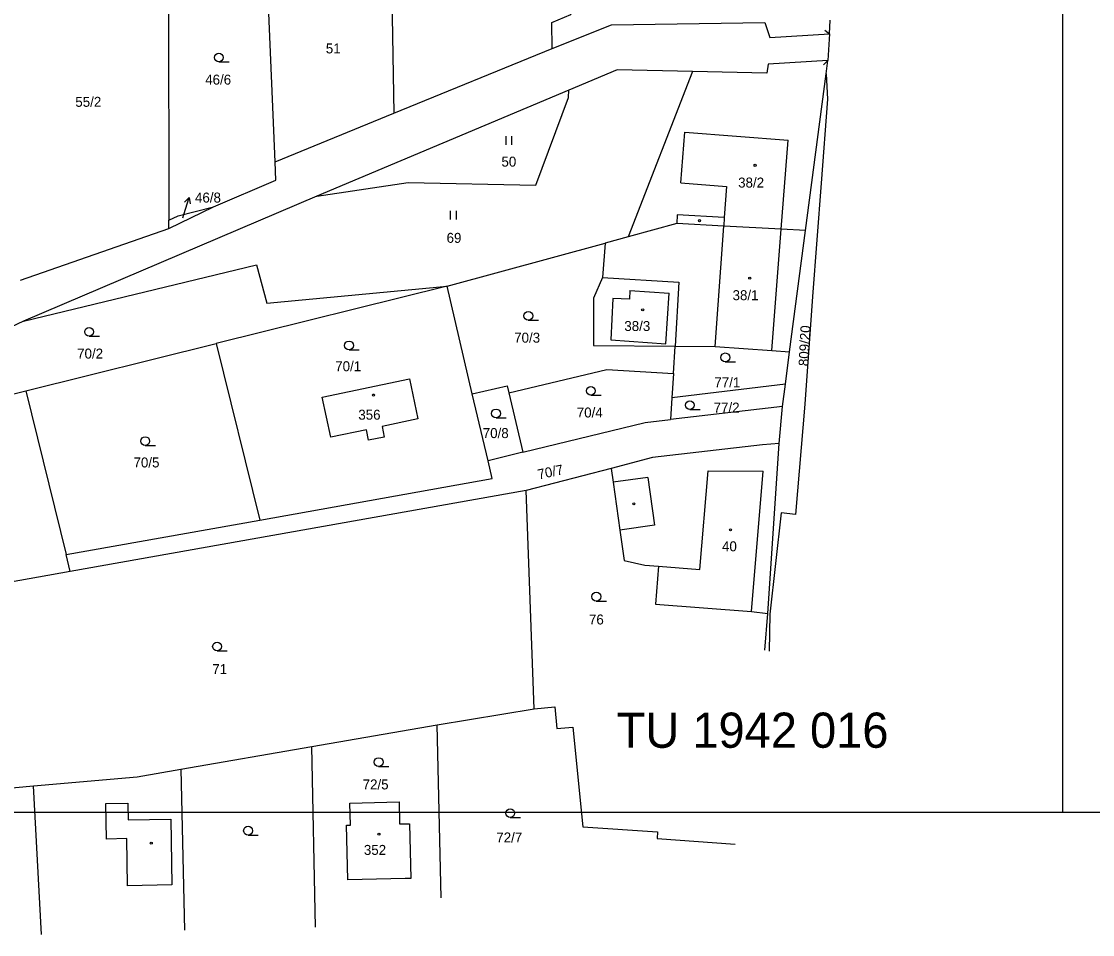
# Model space of a CAD drawing. Extents: x -553916 to -552953, y -1067469 to -1066637.
# Drawn here: x -553477.6 to -553294.9, y -1067431.1 to -1067275.4 of the extents above; entities that cross this region are included whole.
import ezdxf

# ---------------------------------------------------------------- set-up
doc = ezdxf.new("R2010")
doc.units = 0
for name, color, linetype in [('Hranice parcel', 7, 'Continuous'), ('Parcelní čísla', 7, 'Continuous'), ('Pop  PČ popisy', 7, 'Continuous'), ('Vnitřní kresba', 7, 'Continuous'), ('Vrstva 1', 7, 'Continuous'), ('Vrstva 2', 7, 'Continuous'), ('Značky budov', 7, 'Continuous'), ('Značky kultur', 7, 'Continuous')]:
    doc.layers.add(name, color=color, linetype=linetype)

msp = doc.modelspace()

# ---------------------------------------------------------------- linework, layer by layer
at = {"layer": 'Hranice parcel'}
for p, q in [((-553452.56, -1067263.4), (-553452.48, -1067309.26)), ((-553434.32, -1067299.29), (-553435.83, -1067263.59)), ((-553414.54, -1067263.83), (-553414.1, -1067291.02)), ((-553339.78, -1067277.49), (-553339.64, -1067275.16)), ((-553339.78, -1067277.49), (-553340.06, -1067282.03)), ((-553414.1, -1067291.02), (-553387.06, -1067279.96)), ((-553340.36, -1067284.3), (-553340.06, -1067282.03)), ((-553363.12, -1067283.9), (-553374.13, -1067312.09)), ((-553343.86, -1067311), (-553340.36, -1067284.3)), ((-553340.36, -1067284.3), (-553340.08, -1067288.63)), ((-553384.22, -1067287.06), (-553427.2, -1067305.17)), ((-553434.32, -1067299.29), (-553414.1, -1067291.02)), ((-553427.2, -1067305.17), (-553477.28, -1067326.46)), ((-553452.48, -1067310.66), (-553444.86, -1067306.97)), ((-553452.48, -1067310.66), (-553452.48, -1067309.26)), ((-553477.8, -1067319.49), (-553452.48, -1067310.66)), ((-553346.58, -1067331.73), (-553343.86, -1067311)), ((-553404.99, -1067320.53), (-553378.02, -1067313.15)), ((-553378.02, -1067313.15), (-553378.48, -1067319.05)), ((-553374.13, -1067312.09), (-553378.02, -1067313.15)), ((-553404.99, -1067320.53), (-553444.42, -1067330.3)), ((-553400.73, -1067338.86), (-553404.99, -1067320.53)), ((-553378.48, -1067319.05), (-553365.46, -1067319.83)), ((-553365.46, -1067319.83), (-553366.12, -1067330.75)), ((-553477.28, -1067326.46), (-553508.22, -1067341.4)), ((-553476.87, -1067338.35), (-553444.42, -1067330.3)), ((-553444.42, -1067330.3), (-553436.96, -1067360.4)), ((-553366.4, -1067335.42), (-553366.12, -1067330.75)), ((-553347.3, -1067337.24), (-553346.58, -1067331.73)), ((-553394.49, -1067338.71), (-553377.76, -1067334.7)), ((-553377.76, -1067334.7), (-553366.4, -1067335.42)), ((-553366.4, -1067335.42), (-553366.65, -1067339.54)), ((-553504.63, -1067345.23), (-553476.87, -1067338.35)), ((-553476.87, -1067338.35), (-553470.01, -1067366.29)), ((-553398.02, -1067350.28), (-553400.73, -1067338.86)), ((-553394.49, -1067338.71), (-553392.07, -1067348.84)), ((-553347.3, -1067337.24), (-553366.65, -1067339.54)), ((-553347.79, -1067341.01), (-553347.3, -1067337.24)), ((-553366.65, -1067339.54), (-553366.88, -1067343.28)), ((-553347.79, -1067341.01), (-553366.88, -1067343.28)), ((-553348.37, -1067347.33), (-553347.79, -1067341.01)), ((-553350.29, -1067376.34), (-553348.37, -1067347.33)), ((-553392.07, -1067348.84), (-553398.02, -1067350.28)), ((-553397.3, -1067353.33), (-553398.02, -1067350.28)), ((-553377.01, -1067351.59), (-553391.49, -1067355.38)), ((-553436.96, -1067360.4), (-553397.3, -1067353.33)), ((-553391.49, -1067355.38), (-553469.3, -1067369.18)), ((-553390.16, -1067392.62), (-553391.49, -1067355.38)), ((-553470.01, -1067366.29), (-553436.96, -1067360.4)), ((-553469.3, -1067369.18), (-553470.01, -1067366.29)), ((-553469.3, -1067369.18), (-553505.45, -1067375.59)), ((-553350.77, -1067382.61), (-553350.29, -1067376.34)), ((-553349.97, -1067376.47), (-553350.08, -1067382.76)), ((-553406.69, -1067395.35), (-553390.16, -1067392.62)), ((-553390.16, -1067392.62), (-553386.64, -1067392.27)), ((-553428.1, -1067399.03), (-553406.69, -1067395.35)), ((-553406.03, -1067424.86), (-553406.69, -1067395.35)), ((-553450.42, -1067402.9), (-553428.1, -1067399.03)), ((-553427.43, -1067429.84), (-553428.1, -1067399.03)), ((-553450.42, -1067402.9), (-553449.81, -1067430.36)), ((-553504.51, -1067408.36), (-553475.58, -1067405.74)), ((-553474.2, -1067431.11), (-553475.58, -1067405.74))]:
    msp.add_line(p, q, dxfattribs=at)
for points in [[(-553387.06, -1067279.96), (-553387.14, -1067275.52), (-553383.92, -1067274.15), (-553380.89, -1067266)], [(-553387.06, -1067279.96), (-553376.95, -1067275.94), (-553350.82, -1067275.55), (-553349.97, -1067278.1), (-553339.78, -1067277.49)], [(-553340.06, -1067282.03), (-553350.24, -1067282.62), (-553350.46, -1067284.19), (-553363.12, -1067283.9)], [(-553363.12, -1067283.9), (-553376.01, -1067283.6), (-553384.22, -1067287.06)], [(-553427.2, -1067305.17), (-553411.63, -1067302.82), (-553389.87, -1067303.29), (-553384.27, -1067288.32), (-553384.22, -1067287.06)], [(-553340.08, -1067288.63), (-553341.21, -1067302.95), (-553342.64, -1067322.28), (-553343.99, -1067340.66), (-553345.54, -1067359.46), (-553347.99, -1067359.17), (-553349.97, -1067376.47)], [(-553444.86, -1067306.97), (-553434.22, -1067302.44), (-553434.32, -1067299.29)], [(-553452.48, -1067309.26), (-553450.87, -1067308.5), (-553444.86, -1067306.97)], [(-553343.86, -1067311), (-553348.02, -1067310.79), (-553357.81, -1067310.29), (-553365.83, -1067309.82), (-553374.13, -1067312.09)], [(-553477.28, -1067326.46), (-553437.51, -1067316.85), (-553435.74, -1067323.39), (-553404.99, -1067320.53)], [(-553378.48, -1067319.05), (-553380.03, -1067322.56), (-553380.01, -1067330.61), (-553366.12, -1067330.75)], [(-553366.12, -1067330.75), (-553359.25, -1067330.82), (-553349.63, -1067331.51), (-553346.58, -1067331.73)], [(-553426.29, -1067339.42), (-553411.41, -1067336.33), (-553409.99, -1067343.16), (-553416.11, -1067344.46), (-553415.72, -1067346.24), (-553418.41, -1067346.79), (-553418.75, -1067345.01), (-553424.84, -1067346.28), (-553426.29, -1067339.42)], [(-553400.73, -1067338.86), (-553394.78, -1067337.5), (-553394.49, -1067338.71)], [(-553392.07, -1067348.84), (-553371.19, -1067343.77), (-553366.88, -1067343.28)], [(-553348.37, -1067347.33), (-553351.19, -1067347.59), (-553369.94, -1067349.74), (-553377.01, -1067351.59)], [(-553377.01, -1067351.59), (-553376.68, -1067353.95), (-553375.53, -1067362.12), (-553374.8, -1067367.29), (-553371.29, -1067368.08), (-553368.95, -1067368.27), (-553369.45, -1067374.77), (-553353.09, -1067376.03), (-553350.29, -1067376.34)], [(-553386.64, -1067392.27), (-553386.27, -1067395.98), (-553383.55, -1067395.71), (-553381.86, -1067412.72), (-553369.09, -1067413.61), (-553369.18, -1067414.74), (-553355.88, -1067415.67)], [(-553475.58, -1067405.74), (-553457.9, -1067404.18), (-553450.42, -1067402.9)], [(-553421.58, -1067408.69), (-553413.18, -1067408.46), (-553413.1, -1067412.24), (-553412.4, -1067412.22), (-553411.4, -1067412.21), (-553411.17, -1067421.52), (-553412.17, -1067421.55), (-553421.95, -1067421.8), (-553422.19, -1067412.47), (-553421.49, -1067412.45), (-553421.58, -1067408.69)], [(-553451.98, -1067422.65), (-553459.53, -1067422.78), (-553459.64, -1067414.75), (-553463.13, -1067414.82), (-553463.23, -1067408.76), (-553459.46, -1067408.68), (-553459.43, -1067411.53), (-553452.14, -1067411.41), (-553451.98, -1067422.65)]]:
    msp.add_lwpolyline(points, dxfattribs=at)
at = {"layer": 'Pop  PČ popisy'}
for p, q in [((-553449.9, -1067308.26), (-553449.02, -1067305.39)), ((-553449.02, -1067305.39), (-553449.79, -1067306.2)), ((-553449.02, -1067305.39), (-553448.84, -1067306.49)), ((-553450.09, -1067308.86), (-553449.9, -1067308.26))]:
    msp.add_line(p, q, dxfattribs=at)
at = {"layer": 'Vnitřní kresba'}
for p, q in [((-553340.54, -1067276.83), (-553339.78, -1067277.49)), ((-553340.77, -1067282.74), (-553340.06, -1067282.03)), ((-553365.12, -1067302.9), (-553364.45, -1067294.25)), ((-553364.45, -1067294.25), (-553346.84, -1067295.62)), ((-553348.02, -1067310.79), (-553346.84, -1067295.62)), ((-553365.12, -1067302.9), (-553357.33, -1067303.51)), ((-553357.33, -1067303.51), (-553357.71, -1067308.81)), ((-553365.74, -1067308.34), (-553365.83, -1067309.82)), ((-553357.71, -1067308.81), (-553365.74, -1067308.34)), ((-553357.71, -1067308.81), (-553357.81, -1067310.29)), ((-553359.25, -1067330.82), (-553357.81, -1067310.29)), ((-553349.63, -1067331.51), (-553348.02, -1067310.79)), ((-553373.83, -1067321.26), (-553373.9, -1067322.72)), ((-553373.83, -1067321.26), (-553367.11, -1067321.73)), ((-553367.71, -1067330.32), (-553367.11, -1067321.73)), ((-553376.74, -1067322.59), (-553377.06, -1067329.65)), ((-553373.9, -1067322.72), (-553376.74, -1067322.59)), ((-553377.06, -1067329.65), (-553367.71, -1067330.32)), ((-553370.77, -1067353.12), (-553376.68, -1067353.95)), ((-553370.77, -1067353.12), (-553369.62, -1067361.3)), ((-553361.86, -1067368.85), (-553360.49, -1067351.99)), ((-553360.49, -1067351.99), (-553351.11, -1067352.07)), ((-553353.09, -1067376.03), (-553351.11, -1067352.07)), ((-553369.62, -1067361.3), (-553375.53, -1067362.12)), ((-553368.95, -1067368.27), (-553361.86, -1067368.85))]:
    msp.add_line(p, q, dxfattribs=at)
at = {"layer": 'Vrstva 1'}
msp.add_line((-552953.11, -1067410.27), (-553794.11, -1067410.27), dxfattribs=at)
msp.add_lwpolyline([(-553800, -1067410.27), (-553800, -1067100), (-553300, -1067100), (-553300, -1067410.27)], dxfattribs=at)
at = {"layer": 'Značky budov'}
for centre in [(-553352.47, -1067299.9), (-553361.96, -1067309.34), (-553353.38, -1067319.15), (-553371.64, -1067324.53), (-553417.57, -1067339.08), (-553373.16, -1067357.63), (-553356.64, -1067362.06), (-553416.63, -1067413.97), (-553455.47, -1067415.53)]:
    msp.add_circle(centre, 0.175, dxfattribs=at)
at = {"layer": 'Značky kultur'}
for p, q in [((-553443.94, -1067282.25), (-553442.19, -1067282.25)), ((-553394.95, -1067296.43), (-553394.95, -1067294.93)), ((-553393.95, -1067296.43), (-553393.95, -1067294.93)), ((-553404.41, -1067309.15), (-553404.41, -1067307.65)), ((-553403.41, -1067309.15), (-553403.41, -1067307.65)), ((-553391.15, -1067326.33), (-553389.4, -1067326.33)), ((-553466.08, -1067329.06), (-553464.33, -1067329.06)), ((-553421.74, -1067331.37), (-553419.99, -1067331.37)), ((-553357.54, -1067333.41), (-553355.79, -1067333.41)), ((-553380.49, -1067339.11), (-553378.74, -1067339.11)), ((-553363.6, -1067341.56), (-553361.85, -1067341.56)), ((-553396.66, -1067342.97), (-553394.91, -1067342.97)), ((-553456.5, -1067347.69), (-553454.75, -1067347.69)), ((-553379.55, -1067374.22), (-553377.8, -1067374.22)), ((-553444.25, -1067382.73), (-553442.5, -1067382.73)), ((-553416.68, -1067402.44), (-553414.93, -1067402.44)), ((-553394.23, -1067411.16), (-553392.48, -1067411.16)), ((-553438.96, -1067414.14), (-553437.21, -1067414.14))]:
    msp.add_line(p, q, dxfattribs=at)
for centre in [(-553443.94, -1067281.5), (-553391.15, -1067325.58), (-553466.08, -1067328.31), (-553421.74, -1067330.62), (-553357.54, -1067332.66), (-553380.49, -1067338.36), (-553363.6, -1067340.81), (-553396.66, -1067342.22), (-553456.5, -1067346.94), (-553379.55, -1067373.47), (-553444.25, -1067381.98), (-553416.68, -1067401.69), (-553394.23, -1067410.41), (-553438.96, -1067413.39)]:
    msp.add_circle(centre, 0.75, dxfattribs=at)

# ---------------------------------------------------------------- texts
at = {"layer": 'Parcelní čísla'}
for s, p in [('51', (-553425.69, -1067280.81)), ('46/6', (-553446.27, -1067286.13)), ('55/2', (-553468.43, -1067289.92)), ('50', (-553395.73, -1067300.12)), ('38/2', (-553355.35, -1067303.69)), ('46/8', (-553448.01, -1067306.25)), ('69', (-553405.09, -1067313.12)), ('38/1', (-553356.3, -1067322.9)), ('38/3', (-553374.77, -1067328.16)), ('70/3', (-553393.56, -1067330.15)), ('70/2', (-553468.12, -1067332.86)), ('70/1', (-553424.09, -1067335.02)), ('77/1', (-553359.41, -1067337.77)), ('77/2', (-553359.53, -1067342.07)), ('356', (-553420.15, -1067343.29)), ('70/4', (-553382.88, -1067342.91)), ('70/8', (-553398.92, -1067346.42)), ('70/5', (-553458.5, -1067351.43)), ('40', (-553358.1, -1067365.73)), ('76', (-553380.8, -1067378.22)), ('71', (-553445.06, -1067386.68)), ('72/5', (-553419.41, -1067406.35)), ('72/7', (-553396.61, -1067415.4)), ('352', (-553419.2, -1067417.52))]:
    msp.add_text(s, height=1.7, dxfattribs=at).set_placement(p)
for s, rotation, p in [('809/20', 87, (-553343.36, -1067334.19)), ('70/7', 12, (-553389.37, -1067353.49))]:
    msp.add_text(s, height=1.7, rotation=rotation, dxfattribs=at).set_placement(p)
at = {"layer": 'Vrstva 2'}
msp.add_text('TU 1942 016', height=6, dxfattribs=at).set_placement((-553376.09, -1067399.25))

doc.saveas('drawing.dxf')
